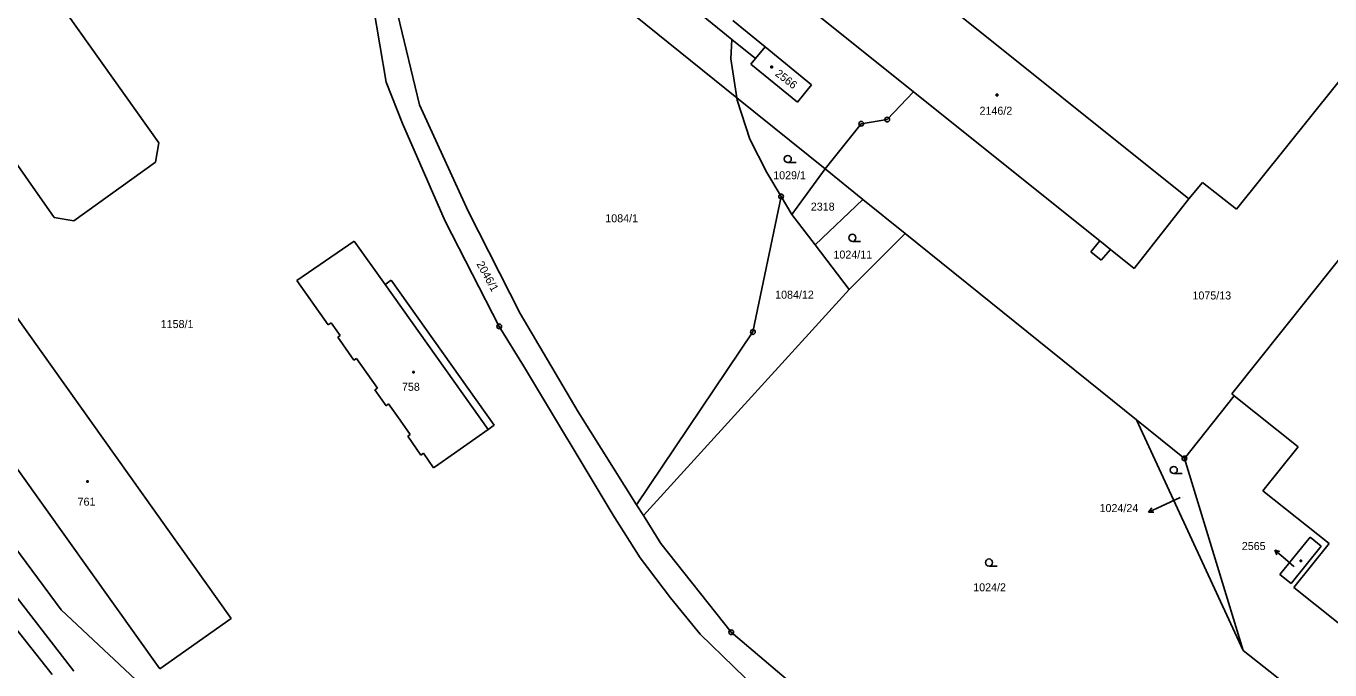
# Model space of a CAD drawing. Extents: x -795483 to -789093, y -1112258 to -1108741.
# Drawn here: x -792603 to -792326, y -1109761.2 to -1109624.3 of the extents above; entities that cross this region are included whole.
import ezdxf

# ---------------------------------------------------------------- set-up
doc = ezdxf.new("R2010")
doc.units = 0
for name, color, linetype in [('Komunikace', 7, 'Continuous'), ('Vrstva 1', 7, 'Continuous'), ('Vrstva 14', 7, 'Continuous'), ('Vrstva 15', 7, 'Continuous'), ('Vrstva 16', 7, 'Continuous'), ('Vrstva 2', 7, 'Continuous'), ('Vrstva 23', 7, 'Continuous'), ('Vrstva 25', 7, 'Continuous'), ('Vrstva 28', 7, 'Continuous')]:
    doc.layers.add(name, color=color, linetype=linetype)

msp = doc.modelspace()

# ---------------------------------------------------------------- linework, layer by layer
at = {"layer": 'Komunikace'}
for p, q in [((-792357.84, -1109724.52), (-792361.82, -1109726.38)), ((-792333.65, -1109739.22), (-792335.44, -1109737.68))]:
    msp.add_line(p, q, dxfattribs=at)
at = {"layer": 'Vrstva 1'}
for p, q in [((-792513.51, -1109590), (-792452, -1109639.59)), ((-792355.96, -1109661.07), (-792431.96, -1109600.14)), ((-792443.73, -1109614.85), (-792414.46, -1109638.3)), ((-792519.4, -1109641.05), (-792525.2, -1109617.17)), ((-792594.35, -1109621.68), (-792574.8, -1109649.17)), ((-792529.23, -1109620.4), (-792526.52, -1109636.29)), ((-792453.05, -1109627.18), (-792460.3, -1109621.29)), ((-792452.83, -1109623.16), (-792446, -1109628.74)), ((-792597.03, -1109665.05), (-792625.13, -1109624.9)), ((-792453.28, -1109631.33), (-792453.05, -1109627.18)), ((-792448.06, -1109631.24), (-792453.05, -1109627.18)), ((-792345.85, -1109663.28), (-792315.38, -1109625.16)), ((-792446, -1109628.74), (-792436.15, -1109636.83)), ((-792452, -1109639.59), (-792453.28, -1109631.33)), ((-792449.04, -1109632.44), (-792448.06, -1109631.24)), ((-792439.13, -1109640.51), (-792449.04, -1109632.44)), ((-792526.52, -1109636.29), (-792523, -1109645.03)), ((-792436.15, -1109636.83), (-792439.13, -1109640.51)), ((-792414.46, -1109638.3), (-792420.04, -1109644.22)), ((-792374.89, -1109670), (-792414.46, -1109638.3)), ((-792509.1, -1109663.72), (-792519.4, -1109641.05)), ((-792452, -1109639.59), (-792433.25, -1109654.71)), ((-792452, -1109639.59), (-792451.92, -1109640.09)), ((-792451.92, -1109640.09), (-792449.24, -1109648.39)), ((-792346.88, -1109702.53), (-792297.84, -1109640.99)), ((-792523, -1109645.03), (-792513.98, -1109665.8)), ((-792425.58, -1109645.1), (-792433.25, -1109654.71)), ((-792420.04, -1109644.22), (-792425.58, -1109645.1)), ((-792574.8, -1109649.17), (-792575.54, -1109653.27)), ((-792449.24, -1109648.39), (-792445.63, -1109655.49)), ((-792575.54, -1109653.27), (-792592.84, -1109665.72)), ((-792440.29, -1109664.4), (-792433.25, -1109654.71)), ((-792433.25, -1109654.71), (-792425.21, -1109661.19)), ((-792445.63, -1109655.49), (-792442.6, -1109660.54)), ((-792353.1, -1109657.6), (-792355.96, -1109661.07)), ((-792353.1, -1109657.6), (-792345.85, -1109663.28)), ((-792442.6, -1109660.54), (-792448.59, -1109689.37)), ((-792442.6, -1109660.54), (-792440.29, -1109664.4)), ((-792435.37, -1109670.87), (-792425.21, -1109661.19)), ((-792425.21, -1109661.19), (-792416.25, -1109668.41)), ((-792367.59, -1109675.85), (-792355.96, -1109661.07)), ((-792592.84, -1109665.72), (-792597.03, -1109665.05)), ((-792513.98, -1109665.8), (-792502.47, -1109688.17)), ((-792498.02, -1109685.41), (-792509.1, -1109663.72)), ((-792440.29, -1109664.4), (-792435.37, -1109670.87)), ((-792416.25, -1109668.41), (-792428.17, -1109680.34)), ((-792416.25, -1109668.41), (-792367.12, -1109708.02)), ((-792533.28, -1109670.03), (-792545.47, -1109678.4)), ((-792526.73, -1109679.3), (-792533.28, -1109670.03)), ((-792435.37, -1109670.87), (-792428.17, -1109680.34)), ((-792376.79, -1109672.3), (-792374.89, -1109670)), ((-792374.58, -1109674.13), (-792376.79, -1109672.3)), ((-792372.65, -1109671.8), (-792374.58, -1109674.13)), ((-792367.59, -1109675.85), (-792372.65, -1109671.8)), ((-792648.83, -1109676.6), (-792595.57, -1109748.42)), ((-792545.47, -1109678.4), (-792538.8, -1109687.82)), ((-792526.73, -1109679.3), (-792525.41, -1109678.37)), ((-792525.41, -1109678.37), (-792503.56, -1109709.15)), ((-792428.17, -1109680.34), (-792471.85, -1109728.39)), ((-792485.75, -1109706.33), (-792498.02, -1109685.41)), ((-792605.41, -1109685.63), (-792559.4, -1109750.29)), ((-792538.8, -1109687.82), (-792538.2, -1109687.4)), ((-792536.26, -1109690.14), (-792538.2, -1109687.4)), ((-792497.34, -1109696.59), (-792502.47, -1109688.17)), ((-792536.78, -1109690.5), (-792536.26, -1109690.14)), ((-792533.36, -1109695.35), (-792536.78, -1109690.5)), ((-792448.59, -1109689.37), (-792473.29, -1109726.11)), ((-792532.84, -1109694.98), (-792533.36, -1109695.35)), ((-792528.38, -1109701.3), (-792532.84, -1109694.98)), ((-792478.3, -1109728.3), (-792497.34, -1109696.59)), ((-792528.9, -1109701.67), (-792528.38, -1109701.3)), ((-792526.51, -1109705.04), (-792528.9, -1109701.67)), ((-792525.99, -1109704.67), (-792526.51, -1109705.04)), ((-792523.53, -1109708.12), (-792525.99, -1109704.67)), ((-792346.37, -1109702.94), (-792356.93, -1109716.24)), ((-792346.37, -1109702.94), (-792346.88, -1109702.53)), ((-792346.37, -1109702.94), (-792332.79, -1109713.75)), ((-792473.29, -1109726.11), (-792485.75, -1109706.33)), ((-792521.4, -1109711.17), (-792523.53, -1109708.12)), ((-792504.87, -1109710.08), (-792515.32, -1109717.44)), ((-792503.56, -1109709.15), (-792504.87, -1109710.08)), ((-792344.46, -1109757.04), (-792367.12, -1109708.02)), ((-792356.93, -1109716.24), (-792367.12, -1109708.02)), ((-792574.61, -1109760.98), (-792609.88, -1109711.5)), ((-792521.92, -1109711.54), (-792521.4, -1109711.17)), ((-792519.11, -1109715.52), (-792521.92, -1109711.54)), ((-792518.59, -1109715.15), (-792519.11, -1109715.52)), ((-792516.42, -1109718.21), (-792518.59, -1109715.15)), ((-792332.79, -1109713.75), (-792340.26, -1109723.13)), ((-792515.32, -1109717.44), (-792516.42, -1109718.21)), ((-792344.46, -1109757.04), (-792356.93, -1109716.24)), ((-792340.26, -1109723.13), (-792326.19, -1109734.34)), ((-792592.84, -1109761.47), (-792621.5, -1109724.44)), ((-792473.29, -1109726.11), (-792471.85, -1109728.39)), ((-792472.55, -1109737.39), (-792478.3, -1109728.3)), ((-792471.85, -1109728.39), (-792468.12, -1109734.31)), ((-792468.12, -1109734.31), (-792453.21, -1109753.19)), ((-792336.62, -1109740.94), (-792330.24, -1109732.98)), ((-792334.22, -1109742.85), (-792327.86, -1109734.89)), ((-792326.19, -1109734.34), (-792333.66, -1109743.71)), ((-792330.24, -1109732.98), (-792327.86, -1109734.89)), ((-792466.13, -1109745.86), (-792472.55, -1109737.39)), ((-792336.62, -1109740.94), (-792334.22, -1109742.85)), ((-792459.77, -1109753.58), (-792466.13, -1109745.86)), ((-792333.66, -1109743.71), (-792319.04, -1109755.37)), ((-792609.81, -1109746.62), (-792597.47, -1109762.19)), ((-792595.57, -1109748.42), (-792548.94, -1109792.07)), ((-792559.4, -1109750.29), (-792574.61, -1109760.98)), ((-792444.74, -1109768.18), (-792459.77, -1109753.58)), ((-792453.21, -1109753.19), (-792420.77, -1109780.63)), ((-792344.46, -1109757.04), (-792293.96, -1109796.98))]:
    msp.add_line(p, q, dxfattribs=at)
at = {"layer": 'Vrstva 16'}
for p, q in [((-792361.82, -1109726.38), (-792364.54, -1109727.65)), ((-792364.54, -1109727.65), (-792363.84, -1109726.77)), ((-792364.54, -1109727.65), (-792363.42, -1109727.68)), ((-792335.44, -1109737.68), (-792337.71, -1109735.72)), ((-792337.71, -1109735.72), (-792337.28, -1109736.75)), ((-792337.71, -1109735.72), (-792336.63, -1109736))]:
    msp.add_line(p, q, dxfattribs=at)
at = {"layer": 'Vrstva 2'}
for p, q in [((-792448.06, -1109631.24), (-792446, -1109628.74)), ((-792374.89, -1109670), (-792372.65, -1109671.8)), ((-792526.73, -1109679.3), (-792504.87, -1109710.08))]:
    msp.add_line(p, q, dxfattribs=at)
at = {"layer": 'Vrstva 23'}
for p, q in [((-792441.18, -1109653.35), (-792439.43, -1109653.35)), ((-792427.46, -1109670.1), (-792425.71, -1109670.1)), ((-792359.18, -1109719.45), (-792357.43, -1109719.45)), ((-792398.43, -1109739.12), (-792396.68, -1109739.12))]:
    msp.add_line(p, q, dxfattribs=at)
for centre in [(-792441.18, -1109652.6), (-792427.46, -1109669.35), (-792359.18, -1109718.7), (-792398.43, -1109738.37)]:
    msp.add_circle(centre, 0.75, dxfattribs=at)
at = {"layer": 'Vrstva 25'}
for p, q in [((-792444.76, -1109632.9), (-792444.46, -1109632.9)), ((-792444.76, -1109633.2), (-792444.76, -1109632.9)), ((-792444.46, -1109633.2), (-792444.76, -1109633.2)), ((-792444.46, -1109632.9), (-792444.46, -1109633.2)), ((-792396.89, -1109638.85), (-792396.59, -1109638.85)), ((-792396.89, -1109639.15), (-792396.89, -1109638.85)), ((-792396.59, -1109639.15), (-792396.89, -1109639.15)), ((-792396.59, -1109638.85), (-792396.59, -1109639.15)), ((-792520.87, -1109697.75), (-792520.57, -1109697.75)), ((-792520.87, -1109698.05), (-792520.87, -1109697.75)), ((-792520.57, -1109698.05), (-792520.87, -1109698.05)), ((-792520.57, -1109697.75), (-792520.57, -1109698.05)), ((-792590.13, -1109720.99), (-792589.83, -1109720.99)), ((-792590.13, -1109721.29), (-792590.13, -1109720.99)), ((-792589.83, -1109721.29), (-792590.13, -1109721.29)), ((-792589.83, -1109720.99), (-792589.83, -1109721.29)), ((-792332.35, -1109737.86), (-792332.05, -1109737.86)), ((-792332.35, -1109738.16), (-792332.35, -1109737.86)), ((-792332.05, -1109737.86), (-792332.05, -1109738.16)), ((-792332.05, -1109738.16), (-792332.35, -1109738.16))]:
    msp.add_line(p, q, dxfattribs=at)
at = {"layer": 'Vrstva 28'}
for centre, radius in [((-792420.04, -1109644.22), 0.5), ((-792425.58, -1109645.1), 0.5), ((-792425.58, -1109645.1), 0.01), ((-792420.04, -1109644.22), 0.01), ((-792442.6, -1109660.54), 0.5), ((-792442.6, -1109660.54), 0.01), ((-792502.47, -1109688.17), 0.5), ((-792502.47, -1109688.17), 0.01), ((-792448.59, -1109689.37), 0.5), ((-792448.59, -1109689.37), 0.01), ((-792356.93, -1109716.24), 0.5), ((-792356.93, -1109716.24), 0.01), ((-792453.21, -1109753.19), 0.5), ((-792453.21, -1109753.19), 0.01)]:
    msp.add_circle(centre, radius, dxfattribs=at)

# ---------------------------------------------------------------- texts
at = {"layer": 'Vrstva 14'}
for s, height, p in [('1029/1', 1.7, (-792444.28, -1109656.9)), ('2318', 1.7, (-792436.29, -1109663.57)), ('1084/1', 1.7, (-792479.95, -1109666.05)), ('1024/11', 1.7, (-792431.48, -1109673.76)), ('1084/12', 1.7, (-792443.87, -1109682.29)), ('1075/13', 1.7, (-792355.21, -1109682.46)), ('1158/1', 1.7, (-792574.4, -1109688.54)), ('1024/24', 0.1, (-792357.84, -1109724.52)), ('1024/2', 1.7, (-792401.79, -1109744.49))]:
    msp.add_text(s, height=height, dxfattribs=at).set_placement(p)
msp.add_text('2046/1', height=1.7, rotation=298.9041, dxfattribs=at).set_placement((-792507.38, -1109674.89))
at = {"layer": 'Vrstva 15'}
msp.add_text('2566', height=1.7, rotation=322.1703, dxfattribs=at).set_placement((-792444.02, -1109634.73))
for s, height, p in [('2146/2', 1.7, (-792400.45, -1109643.19)), ('758', 1.7, (-792523.15, -1109701.87)), ('761', 1.7, (-792592.06, -1109726.29)), ('2565', 0.1, (-792333.65, -1109739.22))]:
    msp.add_text(s, height=height, dxfattribs=at).set_placement(p)
at = {"layer": 'Vrstva 16'}
for s, p in [('1024/24', (-792374.95, -1109727.65)), ('2565', (-792344.73, -1109735.72))]:
    msp.add_text(s, height=1.7, dxfattribs=at).set_placement(p)

doc.saveas('drawing.dxf')
